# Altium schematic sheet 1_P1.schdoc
size 431 x 309 mm; Symbol: Sheet-Symbol_A3; Device: Sheet-Symbol_A3; Company: 嘉立创EDA; Version: V1.0; Page Size: A3; @Project Name: 多功能机械轴体科学计算器; @Page Count: 1; @Update Date: 2023-08-25; @Create Date: 2023-08-25; @Schematic Name: Schematic7_1; @Page No: 1; @Page Name: P1
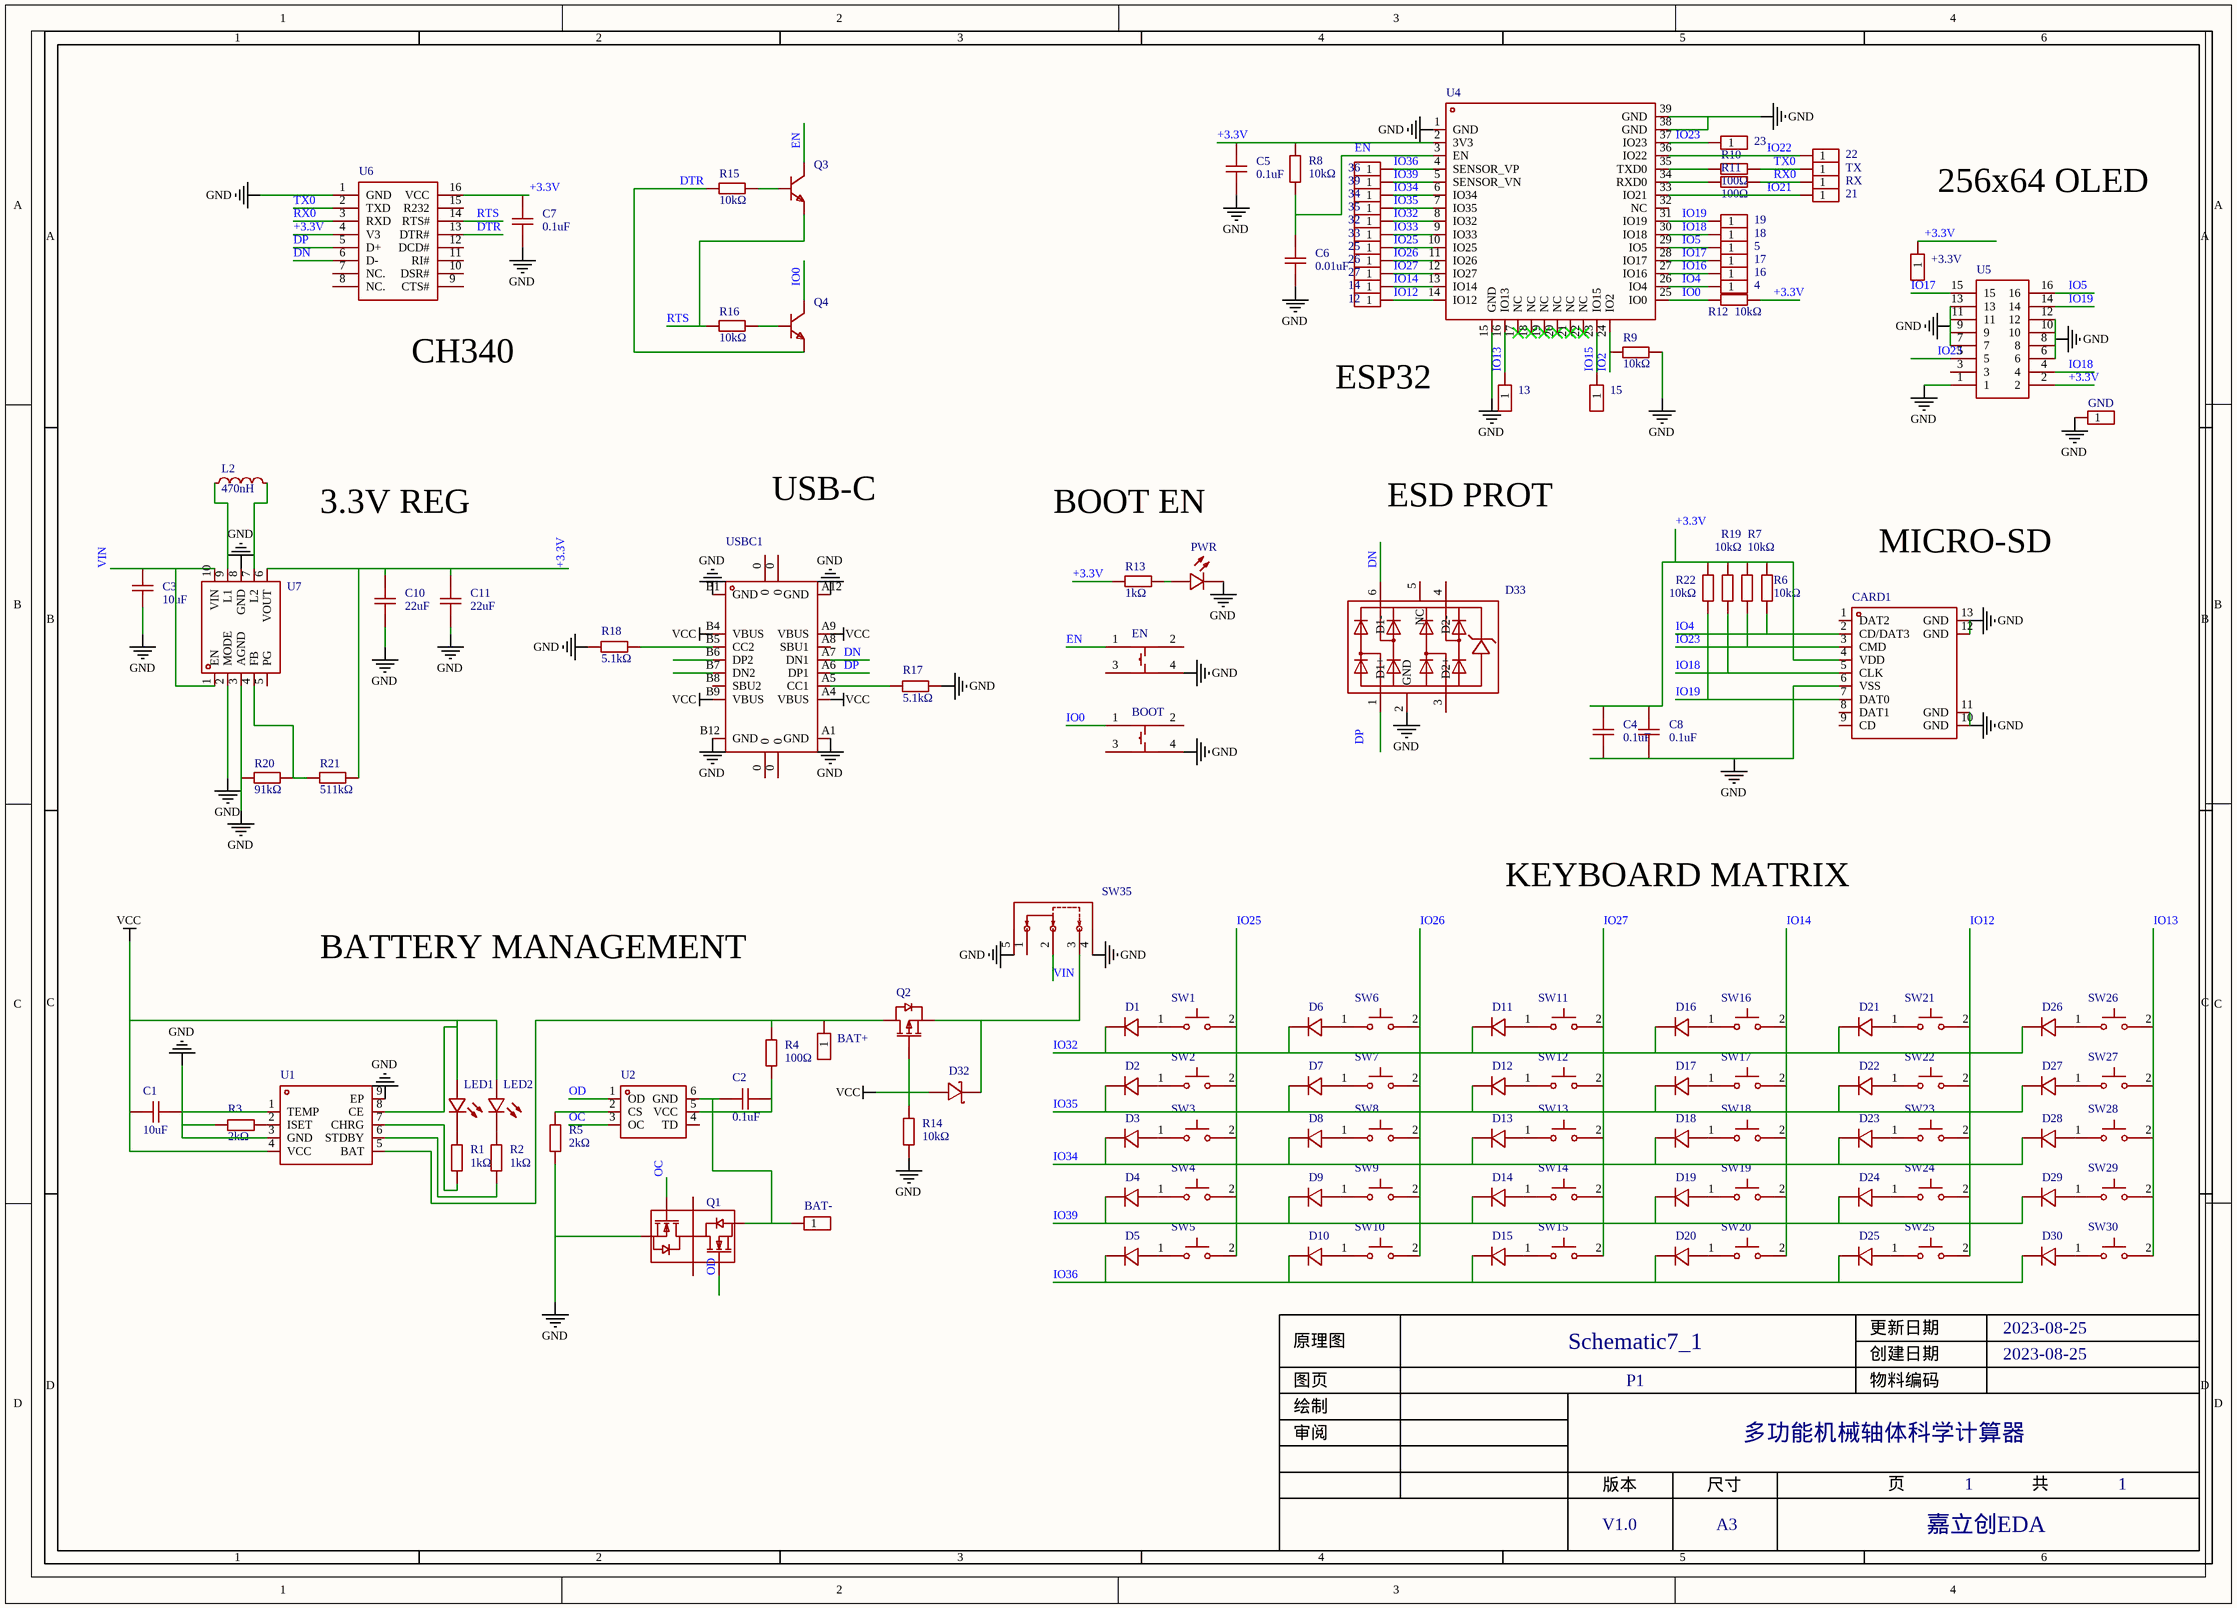
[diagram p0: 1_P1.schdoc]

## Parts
4  2.54-1*1P针  [HDR-TH_1P-P2.54-V-M]  (value not drawn)
5  2.54-1*1P针  [HDR-TH_1P-P2.54-V-M]  (value not drawn)
12  2.54-1*1P针  [HDR-TH_1P-P2.54-V-M]  (value not drawn)
13  2.54-1*1P针  [HDR-TH_1P-P2.54-V-M]  (value not drawn)
14  2.54-1*1P针  [HDR-TH_1P-P2.54-V-M]  (value not drawn)
15  2.54-1*1P针  [HDR-TH_1P-P2.54-V-M]  (value not drawn)
16  2.54-1*1P针  [HDR-TH_1P-P2.54-V-M]  (value not drawn)
17  2.54-1*1P针  [HDR-TH_1P-P2.54-V-M]  (value not drawn)
18  2.54-1*1P针  [HDR-TH_1P-P2.54-V-M]  (value not drawn)
19  2.54-1*1P针  [HDR-TH_1P-P2.54-V-M]  (value not drawn)
21  2.54-1*1P针  [HDR-TH_1P-P2.54-V-M]  (value not drawn)
22  2.54-1*1P针  [HDR-TH_1P-P2.54-V-M]  (value not drawn)
23  2.54-1*1P针  [HDR-TH_1P-P2.54-V-M]  (value not drawn)
25  2.54-1*1P针  [HDR-TH_1P-P2.54-V-M]  (value not drawn)
26  2.54-1*1P针  [HDR-TH_1P-P2.54-V-M]  (value not drawn)
27  2.54-1*1P针  [HDR-TH_1P-P2.54-V-M]  (value not drawn)
32  2.54-1*1P针  [HDR-TH_1P-P2.54-V-M]  (value not drawn)
33  2.54-1*1P针  [HDR-TH_1P-P2.54-V-M]  (value not drawn)
34  2.54-1*1P针  [HDR-TH_1P-P2.54-V-M]  (value not drawn)
35  2.54-1*1P针  [HDR-TH_1P-P2.54-V-M]  (value not drawn)
36  2.54-1*1P针  [HDR-TH_1P-P2.54-V-M]  (value not drawn)
39  2.54-1*1P针  [HDR-TH_1P-P2.54-V-M]  (value not drawn)
+3.3V  2.54-1*1P针  [HDR-TH_1P-P2.54-V-M]  (value not drawn)
BAT+  2.54-1*1P针  [HDR-TH_1P-P2.54-V-M]  (value not drawn)
BAT-  2.54-1*1P针  [HDR-TH_1P-P2.54-V-M]  (value not drawn)
BOOT  DTSM-63N-V-T/R  [KEY-SMD_4P-L6.2-W6.2-P4.50-LS9.0]  (value not drawn)
C1  10uF  [C0603]
C2  0.1uF  [C0603]
C3  10uF  [C0805]
C4  0.1uF  [C0603]
C5  0.1uF  [C0603]
C6  0.01uF  [C0603]
C7  0.1uF  [C0603]
C8  0.1uF  [C0603]
C10  22uF  [C0805]
C11  22uF  [C0805]
CARD1  TF-01A  [TF-SMD_TF-02]  (value not drawn)
D1  C81598  [DO-35_BD2.0-L4.2-P8.20-D0.5-RD]  (value not drawn)
D2  C81598  [DO-35_BD2.0-L4.2-P8.20-D0.5-RD]  (value not drawn)
D3  C81598  [DO-35_BD2.0-L4.2-P8.20-D0.5-RD]  (value not drawn)
D4  C81598  [DO-35_BD2.0-L4.2-P8.20-D0.5-RD]  (value not drawn)
D5  C81598  [DO-35_BD2.0-L4.2-P8.20-D0.5-RD]  (value not drawn)
D6  C81598  [DO-35_BD2.0-L4.2-P8.20-D0.5-RD]  (value not drawn)
D7  C81598  [DO-35_BD2.0-L4.2-P8.20-D0.5-RD]  (value not drawn)
D8  C81598  [DO-35_BD2.0-L4.2-P8.20-D0.5-RD]  (value not drawn)
D9  C81598  [DO-35_BD2.0-L4.2-P8.20-D0.5-RD]  (value not drawn)
D10  C81598  [DO-35_BD2.0-L4.2-P8.20-D0.5-RD]  (value not drawn)
D11  C81598  [DO-35_BD2.0-L4.2-P8.20-D0.5-RD]  (value not drawn)
D12  C81598  [DO-35_BD2.0-L4.2-P8.20-D0.5-RD]  (value not drawn)
D13  C81598  [DO-35_BD2.0-L4.2-P8.20-D0.5-RD]  (value not drawn)
D14  C81598  [DO-35_BD2.0-L4.2-P8.20-D0.5-RD]  (value not drawn)
D15  C81598  [DO-35_BD2.0-L4.2-P8.20-D0.5-RD]  (value not drawn)
D16  C81598  [DO-35_BD2.0-L4.2-P8.20-D0.5-RD]  (value not drawn)
D17  C81598  [DO-35_BD2.0-L4.2-P8.20-D0.5-RD]  (value not drawn)
D18  C81598  [DO-35_BD2.0-L4.2-P8.20-D0.5-RD]  (value not drawn)
D19  C81598  [DO-35_BD2.0-L4.2-P8.20-D0.5-RD]  (value not drawn)
D20  C81598  [DO-35_BD2.0-L4.2-P8.20-D0.5-RD]  (value not drawn)
D21  C81598  [DO-35_BD2.0-L4.2-P8.20-D0.5-RD]  (value not drawn)
D22  C81598  [DO-35_BD2.0-L4.2-P8.20-D0.5-RD]  (value not drawn)
D23  C81598  [DO-35_BD2.0-L4.2-P8.20-D0.5-RD]  (value not drawn)
D24  C81598  [DO-35_BD2.0-L4.2-P8.20-D0.5-RD]  (value not drawn)
D25  C81598  [DO-35_BD2.0-L4.2-P8.20-D0.5-RD]  (value not drawn)
D26  C81598  [DO-35_BD2.0-L4.2-P8.20-D0.5-RD]  (value not drawn)
D27  C81598  [DO-35_BD2.0-L4.2-P8.20-D0.5-RD]  (value not drawn)
D28  C81598  [DO-35_BD2.0-L4.2-P8.20-D0.5-RD]  (value not drawn)
D29  C81598  [DO-35_BD2.0-L4.2-P8.20-D0.5-RD]  (value not drawn)
D30  C81598  [DO-35_BD2.0-L4.2-P8.20-D0.5-RD]  (value not drawn)
D32  SS34  [DO-214AC_L4.3-W2.7-LS5.3-RD]  (value not drawn)
D33  TPD4E1U06DCKR  [SC-70-6_L2.2-W1.3-P0.65-LS2.1-BL]  (value not drawn)
EN  DTSM-63N-V-T/R  [KEY-SMD_4P-L6.2-W6.2-P4.50-LS9.0]  (value not drawn)
GND  2.54-1*1P针  [HDR-TH_1P-P2.54-V-M]  (value not drawn)
L2  470nH  [IND-SMD_L5.7-W5.4]
LED1  19-217/R6C-AL1M2VY/3T  [LED0603-R-RD]  (value not drawn)
LED2  19-217/GHC-YR1S2/3T  [LED0603-R-RD]  (value not drawn)
PWR  19-217/R6C-AL1M2VY/3T  [LED0603-R-RD]  (value not drawn)
Q1  FS8205  [SOT-23-6_L2.9-W1.6-P0.95-LS2.8-BR]  (value not drawn)
Q2  AO3401A  [SOT-23_L2.9-W1.3-P1.90-LS2.4-BR]  (value not drawn)
Q3  S8050  [SOT-23-3_L2.9-W1.3-P1.90-LS2.4-BR]  (value not drawn)
Q4  S8050  [SOT-23-3_L2.9-W1.3-P1.90-LS2.4-BR]  (value not drawn)
R1  1kΩ  [R0603]
R2  1kΩ  [R0603]
R3  2kΩ  [R0603]
R4  100Ω  [R0603]
R5  2kΩ  [R0603]
R6  10kΩ  [R0603]
R7  10kΩ  [R0603]
R8  10kΩ  [R0603]
R9  10kΩ  [R0603]
R10  100Ω  [R0603]
R11  100Ω  [R0603]
R12  10kΩ  [R0603]
R13  1kΩ  [R0603]
R14  10kΩ  [R0603]
R15  10kΩ  [R0603]
R16  10kΩ  [R0603]
R17  5.1kΩ  [R0603]
R18  5.1kΩ  [R0603]
R19  10kΩ  [R0603]
R20  91kΩ  [R0603]
R21  511kΩ  [R0603]
R22  10kΩ  [R0603]
RX  2.54-1*1P针  [HDR-TH_1P-P2.54-V-M]  (value not drawn)
SW1  CPG135001D01  [KEY-TH_CPG135001D0X]  (value not drawn)
SW2  CPG135001D01  [KEY-TH_CPG135001D0X]  (value not drawn)
SW3  CPG135001D01  [KEY-TH_CPG135001D0X]  (value not drawn)
SW4  CPG135001D01  [KEY-TH_CPG135001D0X]  (value not drawn)
SW5  CPG135001D01  [KEY-TH_CPG135001D0X]  (value not drawn)
SW6  CPG135001D01  [KEY-TH_CPG135001D0X]  (value not drawn)
SW7  CPG135001D01  [KEY-TH_CPG135001D0X]  (value not drawn)
SW8  CPG135001D01  [KEY-TH_CPG135001D0X]  (value not drawn)
SW9  CPG135001D01  [KEY-TH_CPG135001D0X]  (value not drawn)
SW10  CPG135001D01  [KEY-TH_CPG135001D0X]  (value not drawn)
SW11  CPG135001D01  [KEY-TH_CPG135001D0X]  (value not drawn)
SW12  CPG135001D01  [KEY-TH_CPG135001D0X]  (value not drawn)
SW13  CPG135001D01  [KEY-TH_CPG135001D0X]  (value not drawn)
SW14  CPG135001D01  [KEY-TH_CPG135001D0X]  (value not drawn)
SW15  CPG135001D01  [KEY-TH_CPG135001D0X]  (value not drawn)
SW16  CPG135001D01  [KEY-TH_CPG135001D0X]  (value not drawn)
SW17  CPG135001D01  [KEY-TH_CPG135001D0X]  (value not drawn)
SW18  CPG135001D01  [KEY-TH_CPG135001D0X]  (value not drawn)
SW19  CPG135001D01  [KEY-TH_CPG135001D0X]  (value not drawn)
SW20  CPG135001D01  [KEY-TH_CPG135001D0X]  (value not drawn)
SW21  CPG135001D01  [KEY-TH_CPG135001D0X]  (value not drawn)
SW22  CPG135001D01  [KEY-TH_CPG135001D0X]  (value not drawn)
SW23  CPG135001D01  [KEY-TH_CPG135001D0X]  (value not drawn)
SW24  CPG135001D01  [KEY-TH_CPG135001D0X]  (value not drawn)
SW25  CPG135001D01  [KEY-TH_CPG135001D0X]  (value not drawn)
SW26  CPG135001D01  [KEY-TH_CPG135001D0X]  (value not drawn)
SW27  CPG135001D01  [KEY-TH_CPG135001D0X]  (value not drawn)
SW28  CPG135001D01  [KEY-TH_CPG135001D0X]  (value not drawn)
SW29  CPG135001D01  [KEY-TH_CPG135001D0X]  (value not drawn)
SW30  CPG135001D01  [KEY-TH_CPG135001D0X]  (value not drawn)
SW35  SK12D07VG4  [SW-TH_SK12D07VG4]  (value not drawn)
TX  2.54-1*1P针  [HDR-TH_1P-P2.54-V-M]  (value not drawn)
U1  4056  [ESOP-8_L4.9-W3.9-P1.27-LS6.0-BL-EP]  (value not drawn)
U2  DW01  [SOT-23-6_L2.9-W1.6-P0.95-LS2.8-BR]  (value not drawn)
U4  ESP32-WROOM-32E-H4  [WIFI-SMD_ESP32-WROOM-32E]  (value not drawn)
U5  oled  [oled3.1]  (value not drawn)
U6  CH340C  [SOP-16_L10.0-W3.9-P1.27-LS6.0-BL]  (value not drawn)
U7  TPS63802DLAR  [VSON-10_L3.0-W2.0-P0.50-TL]  (value not drawn)
USBC1  TYPE-C-31-M-12  [USB-C_SMD-TYPE-C-31-M-12]  (value not drawn)

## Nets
GND: BOOT.4 C1.2 C3.1 C4.1 C5.1 C6.1 C7.1 C8.1 C10.1 C11.1 CARD1.6(VSS) CARD1.10(GND) CARD1.11(GND) CARD1.12(GND) CARD1.13(GND) D33.2(GND) EN.4 GND.1 PWR.2(C) Q1.1(S1) R3.1 R5.1 R9.1 R14.1 R17.2 R18.1 R20.2 SW35.4 SW35.5 U1.1(TEMP) U1.3(GND) U1.9(EP) U4.1(GND) U4.15(GND) U4.38(GND) U4.39(GND) U5.1 U5.6 U5.7 U5.8 U5.9 U5.10 U5.11 U5.12 U5.13 U6.1(GND) U7.2(MODE) U7.3(AGND) U7.8(GND) USBC1.A1(GND) USBC1.A12(GND) USBC1.B1(GND) USBC1.B12(GND)
VCC: C1.1 D32.2(A) LED1.1(A) LED2.1(A) Q2.1(G) R14.2 U1.4(VCC) U1.8(CE) USBC1.A4(VBUS) USBC1.A9(VBUS) USBC1.B4(VBUS) USBC1.B9(VBUS)
+3.3V: +3.3V.1 C4.2 C5.2 C7.2 C8.2 C10.2 C11.2 CARD1.4(VDD) R6.2 R7.2 R8.2 R12.1 R13.1 R19.2 R21.2 R22.2 U4.2(3V3) U5.2 U6.4(V3) U6.16(VCC) U7.6(VOUT)
DN: D33.6(D1-) U6.6(D-) USBC1.A7(DN1)
DP: U6.5(D+) USBC1.A6(DP1)
DTR: Q4.2(E) R15.2 U6.13(DTR#)
EN: C6.2 EN.1 Q3.3(C) R8.1 U4.3(EN)
IO0: BOOT.1 Q4.3(C) R12.2 U4.25(IO0)
IO2: R9.2 U4.24(IO2)
IO4: 4.1 CARD1.2(CD/DAT3) R6.1 U4.26(IO4)
IO5: 5.1 U4.29(IO5) U5.16
IO12: 12.1 SW21.2 SW22.2 SW23.2 SW24.2 SW25.2 U4.14(IO12)
IO13: 13.1 SW26.2 SW27.2 SW28.2 SW29.2 SW30.2 U4.16(IO13)
IO14: 14.1 SW16.2 SW17.2 SW18.2 SW19.2 SW20.2 U4.13(IO14)
IO15: 15.1 U4.23(IO15)
IO16: 16.1 U4.27(IO16)
IO17: 17.1 U4.28(IO17) U5.15
IO18: 18.1 CARD1.5(CLK) R19.1 U4.30(IO18) U5.4
IO19: 19.1 CARD1.7(DAT0) R22.1 U4.31(IO19) U5.14
IO21: 21.1 U4.33(IO21)
IO22: 22.1 U4.36(IO22)
IO23: 23.1 CARD1.3(CMD) R7.1 U4.37(IO23) U5.5
IO25: 25.1 SW1.2 SW2.2 SW3.2 SW4.2 SW5.2 U4.10(IO25)
IO26: 26.1 SW6.2 SW7.2 SW8.2 SW9.2 SW10.2 U4.11(IO26)
IO27: 27.1 SW11.2 SW12.2 SW13.2 SW14.2 SW15.2 U4.12(IO27)
IO32: 32.1 D1.1(C) D6.1(C) D11.1(C) D16.1(C) D21.1(C) D26.1(C) U4.8(IO32)
IO33: 33.1 U4.9(IO33)
IO34: 34.1 D3.1(C) D8.1(C) D13.1(C) D18.1(C) D23.1(C) D28.1(C) U4.6(IO34)
IO35: 35.1 D2.1(C) D7.1(C) D12.1(C) D17.1(C) D22.1(C) D27.1(C) U4.7(IO35)
IO36: 36.1 D5.1(C) D10.1(C) D15.1(C) D20.1(C) D25.1(C) D30.1(C) U4.4(SENSOR_VP)
IO39: 39.1 D4.1(C) D9.1(C) D14.1(C) D19.1(C) D24.1(C) D29.1(C) U4.5(SENSOR_VN)
OC: Q1.6(G1) U2.3(OC)
OD: Q1.4(G2) U2.1(OD)
RTS: Q3.2(E) R16.2 U6.14(RTS#)
RX0: R11.1 RX.1 U6.3(RXD)
TX0: R10.1 TX.1 U6.2(TXD)
VIN: C3.2 SW35.2 U7.1(EN) U7.10(VIN)
NetBAT+_1: BAT+.1 Q2.3(D) R4.2 U1.5(BAT)
NetBAT-_1: BAT-.1 C2.1 Q1.3(S2) U2.6(GND)
NetC2_2: C2.2 R4.1 U2.5(VCC)
NetD1_2: D1.2(A) SW1.1
NetD2_2: D2.2(A) SW2.1
NetD3_2: D3.2(A) SW3.1
NetD4_2: D4.2(A) SW4.1
NetD5_2: D5.2(A) SW5.1
NetD6_2: D6.2(A) SW6.1
NetD7_2: D7.2(A) SW7.1
NetD8_2: D8.2(A) SW8.1
NetD9_2: D9.2(A) SW9.1
NetD10_2: D10.2(A) SW10.1
NetD11_2: D11.2(A) SW11.1
NetD12_2: D12.2(A) SW12.1
NetD13_2: D13.2(A) SW13.1
NetD14_2: D14.2(A) SW14.1
NetD15_2: D15.2(A) SW15.1
NetD16_2: D16.2(A) SW16.1
NetD17_2: D17.2(A) SW17.1
NetD18_2: D18.2(A) SW18.1
NetD19_2: D19.2(A) SW19.1
NetD20_2: D20.2(A) SW20.1
NetD21_2: D21.2(A) SW21.1
NetD22_2: D22.2(A) SW22.1
NetD23_2: D23.2(A) SW23.1
NetD24_2: D24.2(A) SW24.1
NetD25_2: D25.2(A) SW25.1
NetD26_2: D26.2(A) SW26.1
NetD27_2: D27.2(A) SW27.1
NetD28_2: D28.2(A) SW28.1
NetD29_2: D29.2(A) SW29.1
NetD30_2: D30.2(A) SW30.1
NetD32_1: D32.1(K) Q2.2(S) SW35.3
NetL2_1: L2.1 U7.9(L1)
NetL2_2: L2.2 U7.7(L2)
NetLED1_2: LED1.2(C) R1.2
NetLED2_2: LED2.2(C) R2.1
NetPWR_1: PWR.1(A) R13.2
NetQ3_1: Q3.1(B) R15.1
NetQ4_1: Q4.1(B) R16.1
NetR1_1: R1.1 U1.7(CHRG)
NetR2_2: R2.2 U1.6(STDBY)
NetR3_2: R3.2 U1.2(ISET)
NetR5_2: R5.2 U2.2(CS)
NetR10_2: R10.2 U4.35(TXD0)
NetR11_2: R11.2 U4.34(RXD0)
NetR17_1: R17.1 USBC1.A5(CC1)
NetR18_2: R18.2 USBC1.B5(CC2)
NetR20_1: R20.1 R21.1 U7.4(FB)

Not connected (* = marked no-connect by the designer): BOOT 2 3; CARD1 1(DAT2) 8(DAT1) 9(CD); D33 1(D1+) 3(D2+) 4(D2-) 5(NC); EN 2 3; Q1 2(D12) 5(D12); SW35 1; U2 4(TD); U4 17(NC)* 18(NC)* 19(NC)* 20(NC)* 21(NC)* 22(NC)* 32(NC); U5 3; U6 7(NC.) 8(NC.) 9(CTS#) 10(DSR#) 11(RI#) 12(DCD#) 15(R232); U7 5(PG); USBC1 0 A8(SBU1) B6(DP2) B7(DN2) B8(SBU2)

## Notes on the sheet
- 256x64 OLED
- (near U6) CH340
- ESP32
- USB-C
- ESD PROT
- 3.3V REG
- BOOT EN
- MICRO-SD
- KEYBOARD MATRIX
- BATTERY MANAGEMENT
- Labels drawn without touching a wire or pin: DP

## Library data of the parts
4 5 12-19 21-23 25-27 32-36 39 +3.3V BAT+ BAT- GND RX TX = 2.54-1*1P针: 间距:-;总PIN位数:1;排数:1;插针结构:-;行距:-;安装类型:直插;圆针/方针:-;额定电流:-;额定电压:-;配合针长度:-;塑高:-;触头材质:-;触头镀层:-;颜色:黑色;; Manufacturer: BOOMELE(博穆精密); Symbol: Header-Male-2.54_1x1; Add into BOM: yes
BOOT EN = DTSM-63N-V-T/R: 触点电流:50mA;额定电压(DC):12V;电路结构:单刀单掷;安装方式:-;按钮形状:圆形按钮;带灯:-;开关长度:6.2mm;开关宽度:6.2mm;开关高度:7mm;; Manufacturer: 圜达; Add into BOM: yes; Contact Current: 50mA; Voltage Rating (DC): 12V; Circuit: 单刀单掷; Actuator Style: 圆形按钮; Switch Length: 6.2mm; Switch Height: 7mm
C1 = CL10A106KP8NNNC: 容值:10uF;精度:±10%;额定电压:10V;材质(温度系数):X5R;; Manufacturer: SAMSUNG(三星); Add into BOM: yes; Tolerance: ±10%; Voltage Rated: 10V; Temperature Coefficient: X5R
C2 C4-C8 = CC0603KRX7R9BB104: 容值:100nF;精度:±10%;额定电压:50V;材质(温度系数):X7R;; Manufacturer: YAGEO(国巨); Add into BOM: yes; Tolerance: ±10%; Voltage Rated: 50V; Temperature Coefficient: X7R
C3 = CL21A106KAYNNNE_C15850: 容值:10uF;精度:±10%;额定电压:25V;材质(温度系数):X5R;; Manufacturer: SAMSUNG(三星); Add into BOM: yes; Tolerance: ±10%; Voltage Rated: 25V; Temperature Coefficient: X5R
C10 C11 = CL21A226MAQNNNE_C45783: 容值:22uF;精度:±20%;额定电压:25V;温度系数:X5R;; Manufacturer: SAMSUNG(三星); Add into BOM: yes; Tolerance: ±20%; Voltage Rated: 25V; Temperature Coefficient: X5R
CARD1 = TF-01A_C2889258: 卡连接方式:自弹式;卡类型:MicroSD卡(TF卡);连接器类型:卡座;本体最大高度:2mm;工作温度范围:-;; Manufacturer: Yuandi(台湾元迪); Add into BOM: yes; Card Connection Mode: 自弹式; Connector Type: 卡座; Maximum Body Height: 2mm
D1-D30 = 1N4148: 二极管配置:-;功率:500mW;直流反向耐压(Vr):75V;平均整流电流(Io):150mA;正向压降(Vf):1V@10mA;反向电流(Ir):5A@75V;反向恢复时间(trr):4ns;工作温度:+175@(Tvj);; Manufacturer: LGE(鲁光); Symbol: 1N4148_C402212; Add into BOM: yes; Power Dissipation: 500mW; Reverse Voltage (Vr): 75V; Average Rectified Current (Io): 150mA; Reverse Leakage Current: 5A@75V; Reverse Recovery Time (trr): 4ns
D32 = SS34_C8678: 40V,3A,VF=0.55V 3A; Manufacturer: MDD; Add into BOM: yes
D33 = TPD4E1U06DCKR: 极性:Unidirectional;反向关断电压（典型值）:5.5V (Max);击穿电压（最小值）:6.5V;箝位电压:15V (Typ);峰值脉冲电流（10/1000us）:3A (8/20us);; Manufacturer: TI(德州仪器); Add into BOM: yes; Voltage - Breakdown (Min): 6.5V
L2 = MHCI05030-R47M-R8: 电感值:470nH;精度:±20%;额定电流:10A;直流电阻(DCR):8mΩ;; Manufacturer: chilisin(奇力新); Add into BOM: yes; Tolerance: ±20%; Rated Current: 10A; DC Resistance (DCR): 8mΩ
LED1 PWR = 19-217/R6C-AL1M2VY/3T: 发光颜色:红灯;二极管配置:-;透镜颜色:无色透明;主波长:617.5nm;峰值波长:632nm;色温:-;光通量(25时):-;测试电流:5mA;正向电压(VF):2.2V;发光强度:28.5mcd;功率:60mW;发光角度:120°;安装方式:-;工作温度:-40~+85;; Manufacturer: EVERLIGHT(台湾亿光); Add into BOM: yes; Emitted Color: 红灯; Lens Color: 无色透明; Peak Wavelength: 632nm; Forward Current: 5mA; Forward Voltage (VF): 2.2V; Power Dissipation: 60mW; Viewing Angle: 120°
LED2 = 19-217/GHC-YR1S2/3T: 照明颜色:翠绿;色温 - CCT（K）:-;主波长/色坐标:520~535nm;; Manufacturer: EVERLIGHT(台湾亿光); Add into BOM: yes; Illumination Color: 翠绿; Luminous Intensity (IF=20mA): 112~258mcd
Q1 = FS8205: 类型:2个N沟道;漏源电压(Vdss):20V;连续漏极电流(Id):6A;功率(Pd):1W;导通电阻(RDS(on)@Vgs,Id):28mΩ@4.5V,4A;阈值电压(Vgs(th)@Id):1.2V@250A;; Manufacturer: FORTUNE(台湾富晶); Add into BOM: yes; Type: 2个N沟道; Drain Source Voltage (Vdss): 20V; Continuous Drain Current (Id): 6A; Power Dissipation (Pd): 1W
Q2 = AO3401A_C15127: 类型:P沟道;漏源电压(Vdss):30V;连续漏极电流(Id):4A;功率(Pd):1.4W;导通电阻(RDS(on)@Vgs,Id):44mΩ@10V,4.3A;阈值电压(Vgs(th)@Id):1.3V@250A;; Manufacturer: AOS; Add into BOM: yes; Type: P沟道; Drain Source Voltage (Vdss): 30V; Continuous Drain Current (Id): 4A; Power Dissipation (Pd): 1.4W
Q3 Q4 = S8050: Manufacturer: 星海; Symbol: S8050_C2992076; Add into BOM: yes
R1 R2 R13 = RC0603FR-071KL: 电阻类型:厚膜电阻;阻值:1kΩ;精度:±1%;功率:100mW;温度系数:±100ppm/;最大工作电压:75V;工作温度范围:-55~+155;; Manufacturer: YAGEO(国巨); Add into BOM: yes; Tolerance: ±1%; Power(Watts): 100mW; Overload Voltage (Max): 75V
R3 R5 = RC0603FR-072KL: 精度:±1%;阻值:2kΩ;温度系数:±100ppm/;功率:100mW;最大工作电压:75V;工作温度范围:-55~+155;; Manufacturer: YAGEO(国巨); Add into BOM: yes; Tolerance: ±1%; Power(Watts): 100mW; Overload Voltage (Max): 75V
R4 R10 R11 = RC0603FR-07100RL: 电阻类型:厚膜电阻;阻值:100Ω;精度:±1%;功率:100mW;温度系数:±100ppm/;最大工作电压:75V;工作温度范围:-55~+155;; Manufacturer: YAGEO(国巨); Add into BOM: yes; Tolerance: ±1%; Power(Watts): 100mW; Overload Voltage (Max): 75V
R6-R9 R14 R19 R22 = RC0603FR-0710KL: 阻值:10kΩ;精度:±1%;功率:100mW;温度系数:±100ppm/;最大工作电压:75V;工作温度范围:-55~+155;; Manufacturer: YAGEO(国巨); Add into BOM: yes; Tolerance: ±1%; Power(Watts): 100mW; Overload Voltage (Max): 75V
R12 R15 R16 R21 = TR0603B10K0P0525Z: 阻值:10kΩ;精度:±0.1%;温度系数:±25ppm/;功率:100mW;工作温度范围:-55~+155;电阻类型:薄膜电阻;最大工作电压:75V;; Manufacturer: EVER OHMS(天二科技); Symbol: TR0603B10KP05250.1W; Add into BOM: yes; Tolerance: ±0.1%; Temperature Coefficient: ±25ppm/; Power(Watts): 100mW; Overload Voltage (Max): 75V
R17 R18 = 0603WAF5101T5E: 电阻类型:厚膜电阻;阻值:5.1kΩ;精度:±1%;功率:100mW;温度系数:±100ppm/;最大工作电压:75V;工作温度范围:-55~+155;; Manufacturer: UNI-ROYAL(厚声); Add into BOM: yes; Tolerance: ±1%; Power(Watts): 100mW; Overload Voltage (Max): 75V
R20 = 0603WAF9102T5E: 精度:±1%;温度系数:±100ppm/;功率:1/10W;阻值:91kΩ;最大工作电压:75V;工作温度范围:-55~+155;; Manufacturer: UNI-ROYAL(厚声); Add into BOM: yes; Tolerance: ±1%; Power(Watts): 1/10W; Overload Voltage (Max): 75V
SW1-SW30 = CPG135001D01: Manufacturer: Kailh(凯华); Add into BOM: yes
SW35 = SK12D07VG4: 额定电流(DC):500mA;额定电压(DC):50V;额定电流(AC):-;额定电压(AC):-;电路结构:单刀双掷;安装方式:卧插;机械寿命:5000;滑钮形状:矩形柱状;引脚样式:PC引脚;工作温度:-;开关高度:8.8mm;; Manufacturer: SHOU HAN(首韩); Add into BOM: yes; Current Rating (DC): 500mA; Voltage Rating (DC): 50V; Circuit: 单刀双掷; Mechanical Life: 5000; Actuator Style: 矩形柱状; Pin Style: PC引脚; Switch Height: 8.8mm
U1 = 4056: 充电电池的类型:-;电池单元组数:-;最大充电电流:-;充满的电池组电压:-;最大供应电压:-;; Manufacturer: RONGHE(融和); Add into BOM: yes
U2 = DW01: 充电电池的类型:-;电池单元组数:-;最大充电电流:-;充满的电池组电压:-;最大供应电压:-;; Manufacturer: PJSEMI(平晶微); Symbol: DW01_C686633; Add into BOM: yes
U4 = ESP32-WROOM-32E-H4: 命名更改，4MB即H4，为尾缀，模组丝印更改为H4，H为高温105°C，软硬件无更改; Manufacturer: ESPRESSIF(乐鑫); Add into BOM: yes
U5 = oled: Convert to PCB: yes
U6 = CH340C: 类型:Transceiver;协议类别:USB 2.0;驱动器/接收器数:-;数据速率:2Mbps;; Manufacturer: WCH(南京沁恒); Add into BOM: yes; Protocol: USB 2.0; Data Rate: 2Mbps; Supply Voltage: 3.3V, 5V
U7 = TPS63802DLAR_C2845237: Manufacturer: TI(德州仪器); Add into BOM: yes
USBC1 = TYPE-C-31-M-12: 连接器类型:Type-C;标准:-;公母:母座;触点数量:16;端口数量:1;额定电流 - 电源:250mA;; Manufacturer: 韩国韩荣; Add into BOM: yes; Connector Type: Type-C; Gender: 母座; Number of Contacts: 16; Number of Ports: 1; Current Rating - Power (Max): 250mA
